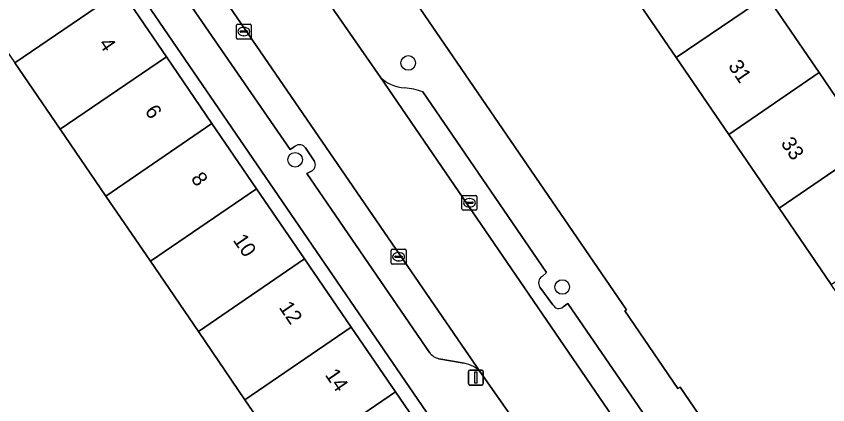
# Model space of a CAD drawing. Extents: x 157445 to 158888, y 383061 to 384688.
# Drawn here: x 158256.9 to 158311.3, y 383555.3 to 383581.3 of the extents above; entities that cross this region are included whole.
import ezdxf

# ---------------------------------------------------------------- set-up
doc = ezdxf.new("R2010")
doc.units = 0
for name, color, linetype in [('IMGEO_Boom', 7, 'Continuous'), ('IMGEO_Erf', 7, 'Continuous'), ('IMGEO_Kolk', 7, 'Continuous'), ('IMGEO_Lichtmast', 7, 'Continuous'), ('IMGEO_Pand', 7, 'Continuous'), ('IMGEO_Pand_nummerreeks', 7, 'Continuous'), ('IMGEO_Parkeervlak_open', 7, 'Continuous'), ('IMGEO_Rijbaan_lokaal_open', 7, 'Continuous'), ('IMGEO_Voetpad_open', 7, 'Continuous')]:
    doc.layers.add(name, color=color, linetype=linetype)

msp = doc.modelspace()

# ---------------------------------------------------------------- linework, layer by layer
at = {"layer": 'IMGEO_Boom'}
for centre in [(158283.176, 383578.158), (158275.601, 383571.669), (158293.495, 383563.147)]:
    msp.add_circle(centre, 0.489, dxfattribs=at)
at = {"layer": 'IMGEO_Erf'}
for points in [[(158322.051, 383583.576), (158306.438, 383606.562), (158284.721, 383591.707), (158280.579, 383588.831), (158280.654, 383586.674), (158297.815, 383561.626), (158297.69, 383561.544), (158301.237, 383556.346), (158301.401, 383556.432), (158316.985, 383533.617)], [(158256.313, 383551.418), (158259.498, 383546.89), (158261.771, 383543.66), (158259.723, 383542.219), (158261.171, 383540.091), (158263.271, 383541.527), (158265.465, 383538.411), (158278.195, 383546.876), (158275.199, 383551.26), (158272.237, 383555.595), (158269.115, 383560.163), (158265.897, 383564.872), (158262.909, 383569.245), (158259.856, 383573.712), (158256.815, 383578.162)]]:
    msp.add_lwpolyline(points, dxfattribs=at)
for points in [[(158330.367, 383544.545), (158326.236, 383541.727), (158322.107, 383547.78), (158318.545, 383553.002), (158315.03, 383558.156), (158311.516, 383563.307), (158308.027, 383568.422), (158304.653, 383573.369), (158301.139, 383578.52), (158297.591, 383583.722), (158293.982, 383589.013), (158290.337, 383594.357), (158296.41, 383598.499), (158299.227, 383594.369), (158300.055, 383593.156), (158303.664, 383587.864), (158307.212, 383582.663), (158310.726, 383577.511), (158314.099, 383572.565), (158317.588, 383567.449), (158321.102, 383562.298), (158324.617, 383557.144), (158328.18, 383551.921), (158332.308, 383545.869)], [(158261.412, 383588.358), (158260.646, 383587.833), (158263.932, 383583.024), (158266.973, 383578.575), (158270.026, 383574.107), (158273.013, 383569.736), (158276.233, 383565.025), (158279.354, 383560.458), (158282.316, 383556.124), (158285.312, 383551.74), (158286.103, 383552.281)]]:
    msp.add_lwpolyline(points, close=True, dxfattribs=at)
at = {"layer": 'IMGEO_Kolk'}
for p, q in [((158271.659, 383579.833), (158271.659, 383580.685)), ((158271.734, 383580.759), (158272.586, 383580.759)), ((158272.147, 383580.539), (158272.172, 383580.539)), ((158272.66, 383580.685), (158272.66, 383579.833)), ((158271.918, 383580.253), (158271.918, 383580.265)), ((158272.356, 383580.216), (158271.958, 383580.216)), ((158271.961, 383580.302), (158272.359, 383580.302)), ((158272.402, 383580.265), (158272.402, 383580.253)), ((158272.586, 383579.759), (158271.734, 383579.759)), ((158272.17, 383579.979), (158272.145, 383579.979)), ((158286.781, 383568.363), (158286.781, 383569.215)), ((158286.856, 383569.289), (158287.708, 383569.289)), ((158287.782, 383569.215), (158287.782, 383568.363)), ((158287.04, 383568.783), (158287.04, 383568.795)), ((158287.478, 383568.746), (158287.08, 383568.746)), ((158287.083, 383568.832), (158287.481, 383568.832)), ((158287.269, 383569.069), (158287.294, 383569.069)), ((158287.524, 383568.795), (158287.524, 383568.783)), ((158287.708, 383568.289), (158286.856, 383568.289)), ((158287.292, 383568.509), (158287.267, 383568.509)), ((158282.03, 383564.751), (158282.03, 383565.603)), ((158282.105, 383565.677), (158282.957, 383565.677)), ((158282.518, 383565.457), (158282.543, 383565.457)), ((158283.031, 383565.603), (158283.031, 383564.751)), ((158282.289, 383565.171), (158282.289, 383565.183)), ((158282.727, 383565.134), (158282.329, 383565.134)), ((158282.332, 383565.22), (158282.73, 383565.22)), ((158282.541, 383564.897), (158282.516, 383564.897)), ((158282.773, 383565.183), (158282.773, 383565.171)), ((158282.957, 383564.677), (158282.105, 383564.677))]:
    msp.add_line(p, q, dxfattribs=at)
for points in [[(158271.659, 383579.833), (158271.659, 383580.685)], [(158271.734, 383580.759), (158272.586, 383580.759)], [(158272.66, 383580.685), (158272.66, 383579.833)], [(158272.586, 383579.759), (158271.734, 383579.759)], [(158286.781, 383568.363), (158286.781, 383569.215)], [(158286.856, 383569.289), (158287.708, 383569.289)], [(158287.782, 383569.215), (158287.782, 383568.363)], [(158287.708, 383568.289), (158286.856, 383568.289)], [(158282.03, 383564.751), (158282.03, 383565.603)], [(158282.105, 383565.677), (158282.957, 383565.677)], [(158283.031, 383565.603), (158283.031, 383564.751)], [(158282.957, 383564.677), (158282.105, 383564.677)]]:
    msp.add_lwpolyline(points, dxfattribs=at)
for centre, radius, start, end in [((158271.736, 383580.683), 0.0765, 91.552, 178.448), ((158271.736, 383580.683), 0.0765, 91.552, 178.448), ((158272.584, 383580.683), 0.0765, 1.552, 88.448), ((158272.584, 383580.683), 0.0765, 1.552, 88.448), ((158271.958, 383580.262), 0.0403, 85.8775, 175.7526), ((158271.955, 383580.252), 0.0366, 178.938, 274.7102), ((158272.359, 383580.259), 0.043, 264.8664, 352.4533), ((158272.363, 383580.264), 0.0386, 1.7309, 96.639), ((158271.736, 383579.835), 0.0765, 181.552, 268.448), ((158271.736, 383579.835), 0.0765, 181.552, 268.448), ((158272.584, 383579.835), 0.0765, 271.552, 358.448), ((158272.584, 383579.835), 0.0765, 271.552, 358.448), ((158286.858, 383569.213), 0.0765, 91.552, 178.448), ((158286.858, 383569.213), 0.0765, 91.552, 178.448), ((158287.706, 383569.213), 0.0765, 1.552, 88.448), ((158287.706, 383569.213), 0.0765, 1.552, 88.448), ((158287.08, 383568.792), 0.0403, 85.8775, 175.7526), ((158287.077, 383568.782), 0.0366, 178.938, 274.7102), ((158287.481, 383568.789), 0.043, 264.8664, 352.4533), ((158287.485, 383568.794), 0.0386, 1.7309, 96.639), ((158286.858, 383568.365), 0.0765, 181.552, 268.448), ((158286.858, 383568.365), 0.0765, 181.552, 268.448), ((158287.706, 383568.365), 0.0765, 271.552, 358.448), ((158287.706, 383568.365), 0.0765, 271.552, 358.448), ((158282.107, 383565.601), 0.0765, 91.552, 178.448), ((158282.107, 383565.601), 0.0765, 91.552, 178.448), ((158282.955, 383565.601), 0.0765, 1.552, 88.448), ((158282.955, 383565.601), 0.0765, 1.552, 88.448), ((158282.329, 383565.18), 0.0403, 85.8775, 175.7526), ((158282.326, 383565.17), 0.0366, 178.938, 274.7102), ((158282.73, 383565.177), 0.043, 264.8664, 352.4533), ((158282.734, 383565.182), 0.0386, 1.7309, 96.639), ((158282.107, 383564.753), 0.0765, 181.552, 268.448), ((158282.107, 383564.753), 0.0765, 181.552, 268.448), ((158282.955, 383564.753), 0.0765, 271.552, 358.448), ((158282.955, 383564.753), 0.0765, 271.552, 358.448)]:
    msp.add_arc(centre, radius, start, end, dxfattribs=at)
for centre, major_axis, ratio, start_param, end_param in [((158272.146, 383580.259), (-0.387, 0.002), 0.722429, 4.712389, 7.853982), ((158272.171, 383580.259), (-0.39, 0.002), 0.717154, 1.570796, 4.712389), ((158287.268, 383568.789), (-0.387, 0.002), 0.722429, 4.712389, 7.853982), ((158287.293, 383568.789), (-0.39, 0.002), 0.717154, 1.570796, 4.712389), ((158282.517, 383565.177), (-0.387, 0.002), 0.722429, 4.712389, 7.853982), ((158282.542, 383565.177), (-0.39, 0.002), 0.717154, 1.570796, 4.712389)]:
    msp.add_ellipse(centre, major_axis=major_axis, ratio=ratio, start_param=start_param, end_param=end_param, dxfattribs=at)
at = {"layer": 'IMGEO_Lichtmast'}
for p, q in [((158287.216, 383556.682), (158287.216, 383557.482)), ((158287.216, 383557.482), (158287.216, 383556.682)), ((158287.316, 383557.582), (158288.106, 383557.582)), ((158288.106, 383557.582), (158287.316, 383557.582)), ((158288.206, 383557.482), (158288.206, 383556.682)), ((158288.206, 383556.682), (158288.206, 383557.482)), ((158288.106, 383556.582), (158287.316, 383556.582)), ((158287.316, 383556.582), (158288.106, 383556.582))]:
    msp.add_line(p, q, dxfattribs=at)
msp.add_lwpolyline([(158287.636, 383557.457), (158287.786, 383557.457), (158287.786, 383556.707), (158287.636, 383556.707), (158287.636, 383557.457)], dxfattribs=at)
for centre, start, end in [((158287.316, 383557.482), 90, 180), ((158287.316, 383557.482), 90, 180), ((158288.106, 383557.482), 0, 90), ((158288.106, 383557.482), 360, 90), ((158287.316, 383556.682), 180, 270), ((158287.316, 383556.682), 180, 270), ((158288.106, 383556.682), 270, 0), ((158288.106, 383556.682), 270, 0)]:
    msp.add_arc(centre, 0.1, start, end, dxfattribs=at)
at = {"layer": 'IMGEO_Pand'}
for points in [[(158263.932, 383583.024), (158260.646, 383587.833), (158260.521, 383587.747), (158256.519, 383585.012), (158253.53, 383582.969), (158256.815, 383578.162)], [(158297.591, 383583.722), (158301.139, 383578.52), (158307.212, 383582.663), (158303.664, 383587.864)], [(158266.973, 383578.575), (158263.932, 383583.024), (158256.815, 383578.162), (158259.856, 383573.712)], [(158304.653, 383573.369), (158310.726, 383577.511), (158307.212, 383582.663), (158301.139, 383578.52)], [(158262.909, 383569.245), (158270.026, 383574.107), (158266.973, 383578.575), (158259.856, 383573.712)], [(158304.653, 383573.369), (158308.027, 383568.422), (158314.099, 383572.565), (158310.726, 383577.511)], [(158273.013, 383569.736), (158270.026, 383574.107), (158262.909, 383569.245), (158265.897, 383564.872)], [(158314.099, 383572.565), (158308.027, 383568.422), (158311.516, 383563.307), (158317.588, 383567.449)], [(158273.013, 383569.736), (158265.897, 383564.872), (158269.115, 383560.163), (158276.233, 383565.025)], [(158272.237, 383555.595), (158279.354, 383560.458), (158276.233, 383565.025), (158269.115, 383560.163)], [(158272.237, 383555.595), (158275.199, 383551.26), (158282.316, 383556.124), (158279.354, 383560.458)], [(158282.316, 383556.124), (158275.199, 383551.26), (158278.195, 383546.876), (158281.184, 383548.919), (158285.312, 383551.74)]]:
    msp.add_lwpolyline(points, close=True, dxfattribs=at)
at = {"layer": 'IMGEO_Parkeervlak_open'}
for points in [[(158288.053, 383557.407), (158264.184, 383592.177)], [(158264.301, 383588.414), (158266.512, 383585.07), (158275.264, 383572.371), (158275.604, 383572.585)], [(158281.287, 383577.232), (158297.166, 383554.041), (158299.891, 383550.174)], [(158292.152, 383563.862), (158292.441, 383564.128), (158284.159, 383576.219)], [(158276.302, 383572.464), (158276.869, 383571.608)], [(158276.735, 383570.927), (158276.39, 383570.751), (158284.594, 383558.767)], [(158292.872, 383561.964), (158292.007, 383563.134)], [(158300.074, 383550.728), (158301.138, 383551.491), (158293.884, 383562.049), (158293.552, 383561.819)], [(158285.233, 383558.343), (158286.925, 383558.045)]]:
    msp.add_lwpolyline(points, dxfattribs=at)
for centre, radius, start, end in [((158283.089, 383579.032), 2.547, 224.9691, 266.3694), ((158282.666, 383572.366), 4.132, 68.8109, 86.3583), ((158275.891, 383572.165), 0.508, 36.0034, 124.3274), ((158276.475, 383571.332), 0.481, 302.7369, 34.9994), ((158292.428, 383563.429), 0.514, 122.4699, 215.0011), ((158293.265, 383562.138), 0.429, 203.8927, 312.0329), ((158285.511, 383559.455), 1.147, 216.8986, 255.9699), ((158286.57, 383556.101), 1.976, 41.3624, 79.6523)]:
    msp.add_arc(centre, radius, start, end, dxfattribs=at)
at = {"layer": 'IMGEO_Rijbaan_lokaal_open'}
msp.add_lwpolyline([(158276.368, 383584.356), (158274.995, 383586.467), (158270.806, 383592.574), (158267.986, 383596.629), (158259.75, 383608.744), (158255.078, 383605.443), (158256.84, 383602.832), (158258.908, 383599.874), (158259.046, 383599.735), (158261, 383596.831), (158262.585, 383594.528), (158263.501, 383593.197), (158264.184, 383592.177), (158288.053, 383557.407), (158290.293, 383554.184), (158292.53, 383550.856), (158297.166, 383554.041), (158281.287, 383577.232)], close=True, dxfattribs=at)
at = {"layer": 'IMGEO_Voetpad_open'}
for points in [[(158246.999, 383617.179), (158244.36, 383621.051), (158243.465, 383620.474), (158236.284, 383630.945), (158234.717, 383625.799), (158237.929, 383620.937), (158241.491, 383615.546), (158253.203, 383598.26), (158253.341, 383598.153), (158256.385, 383593.609), (158256.493, 383593.672), (158259.462, 383589.365), (158259.632, 383589.105), (158260.521, 383587.747), (158260.646, 383587.833), (158261.412, 383588.358), (158286.103, 383552.281), (158287.042, 383550.909), (158313.103, 383512.83)], [(158301.401, 383556.432), (158301.237, 383556.346), (158297.69, 383561.544), (158297.815, 383561.626), (158280.654, 383586.674), (158278.116, 383590.363), (158275.903, 383587.003), (158274.995, 383586.467), (158276.368, 383584.356), (158281.287, 383577.232)], [(158275.604, 383572.585), (158275.264, 383572.371), (158266.512, 383585.07), (158264.301, 383588.414)], [(158284.159, 383576.219), (158292.441, 383564.128), (158292.152, 383563.862)], [(158276.869, 383571.608), (158276.302, 383572.464)], [(158284.594, 383558.767), (158276.39, 383570.751), (158276.735, 383570.927)], [(158292.007, 383563.134), (158292.872, 383561.964)], [(158293.552, 383561.819), (158293.884, 383562.049), (158301.138, 383551.491), (158300.074, 383550.728)], [(158286.925, 383558.045), (158285.233, 383558.343)], [(158292.914, 383550.25), (158292.53, 383550.856), (158292.163, 383550.61), (158289.88, 383553.911), (158290.293, 383554.184), (158288.053, 383557.407)], [(158333.845, 383508.772), (158325.365, 383521.154), (158322.136, 383525.869), (158322.372, 383525.976), (158320.263, 383529.073), (158322.521, 383530.674), (158321.142, 383532.711), (158318.872, 383531.117), (158318.38, 383531.84), (158317.112, 383533.721), (158316.985, 383533.617), (158301.401, 383556.432)]]:
    msp.add_lwpolyline(points, dxfattribs=at)
for centre, radius, start, end in [((158283.089, 383579.032), 2.547, 224.9691, 266.3694), ((158282.666, 383572.366), 4.132, 68.8109, 86.3583), ((158275.891, 383572.165), 0.508, 36.0034, 124.3274), ((158276.475, 383571.332), 0.481, 302.7369, 34.9994), ((158292.428, 383563.429), 0.514, 122.4699, 215.0011), ((158293.265, 383562.138), 0.429, 203.8927, 312.0329), ((158285.511, 383559.455), 1.147, 216.8986, 255.9699), ((158286.57, 383556.101), 1.976, 41.3624, 79.6523)]:
    msp.add_arc(centre, radius, start, end, dxfattribs=at)

# ---------------------------------------------------------------- texts
at = {"layer": 'IMGEO_Pand_nummerreeks'}
for s, rotation, p in [('4', 304.3487, (158262.408, 383579.442)), ('31', 304.298, (158304.581, 383577.946)), ('6', 304.3487, (158265.491, 383574.931)), ('33', 304.298, (158308.107, 383572.776)), ('8', 304.3487, (158268.576, 383570.416)), ('10', 304.3487, (158271.399, 383566.284)), ('12', 304.3487, (158274.48, 383561.778)), ('14', 304.3487, (158277.565, 383557.264))]:
    msp.add_text(s, height=1, rotation=rotation, dxfattribs=at).set_placement(p)

doc.saveas('drawing.dxf')
